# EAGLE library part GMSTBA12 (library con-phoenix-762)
PHOENIX
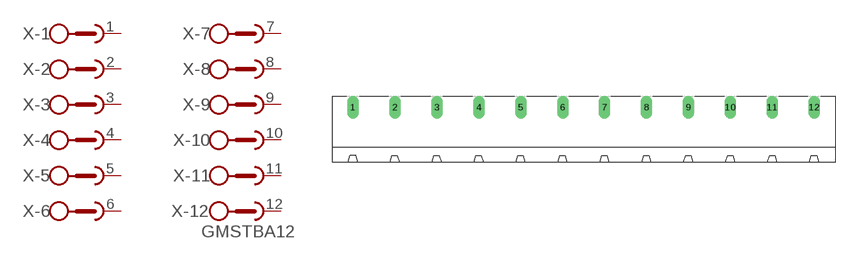
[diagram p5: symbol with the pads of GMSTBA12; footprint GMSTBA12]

Designator prefix X; gates -1=SKB -2=SKB -3=SKB -4=SKB -5=SKB -6=SKB -7=SKB -8=SKB -9=SKB -10=SKB -11=SKB -12=SKBV

## GMSTBA12 (MPN: 1757349; OC_FARNELL: 3705250; OC_NEWARK: 71C4169)  [GMSTBA12]
1  -1:1  pas
2  -2:1  pas
3  -3:1  pas
4  -4:1  pas
5  -5:1  pas
6  -6:1  pas
7  -7:1  pas
8  -8:1  pas
9  -9:1  pas
10  -10:1  pas
11  -11:1  pas
12  -12:1  pas

## Footprint GMSTBA12 (pad centres in mm)
PHOENIX
drill 1.397 long: 1 -41.91,5.08; 2 -34.29,5.08; 3 -26.67,5.08; 4 -19.05,5.08; 5 -11.43,5.08; 6 -3.81,5.08; 7 3.81,5.08; 8 11.43,5.08; 9 19.05,5.08; 10 26.67,5.08; 11 34.29,5.08; 12 41.91,5.08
